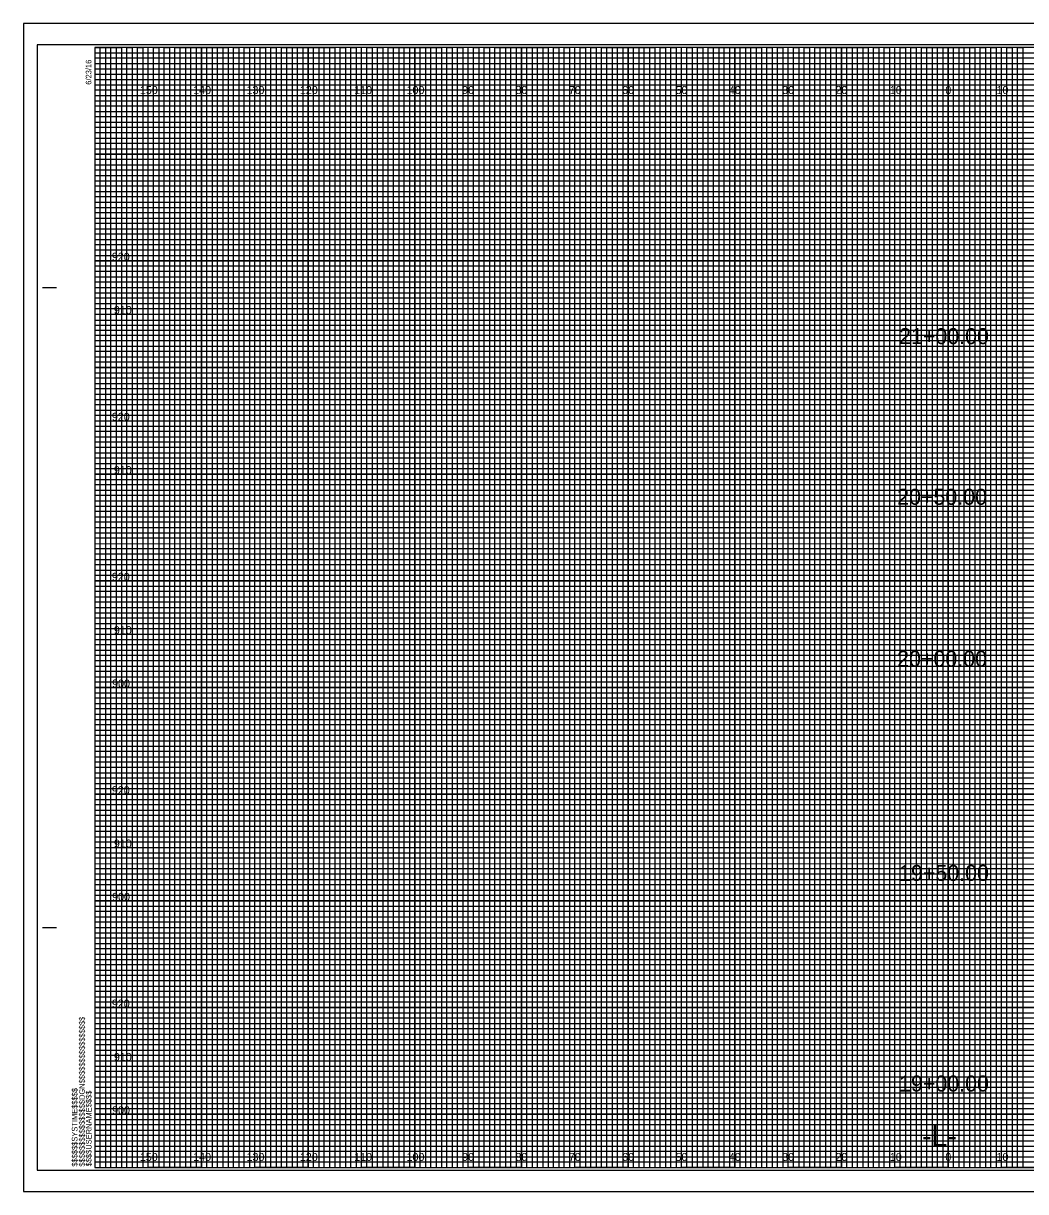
# Model space of a CAD drawing. Extents: x -13 to 364, y -4 to 214.
# Drawn here: x -13.4 to 174.5, y -4.5 to 214.5 of the extents above; entities that cross this region are included whole.
import ezdxf

# ---------------------------------------------------------------- set-up
doc = ezdxf.new("R2010")
doc.units = 0
for name, color, linetype in [('Prop SS Cut Line', 7, 'Continuous'), ('Prop SS Fill Line', 7, 'Continuous'), ('Prop XS Alignment Label', 7, 'Continuous'), ('Prop XS Elevation Labels', 7, 'Continuous'), ('Prop XS Label Text', 7, 'Continuous'), ('Prop XS Shear Point Label', 7, 'Continuous'), ('Prop XS Station Labels', 7, 'Continuous'), ('Scratch_Level_3', 7, 'Continuous'), ('Sheet Cross Section Grid Minor 2 CELL', 7, 'Continuous'), ('Sheet Cutting Line CELL', 7, 'Continuous'), ('Sheet DOT Grid CELL', 7, 'Continuous'), ('Sheet Plot Border Inside CELL', 7, 'Continuous'), ('Sheet Plot Border Outside CELL', 7, 'Continuous')]:
    doc.layers.add(name, color=color, linetype=linetype)

msp = doc.modelspace()

# ---------------------------------------------------------------- linework, layer by layer
at = {"layer": 'Prop SS Cut Line'}
for p, q in [((10, 210), (0, 210)), ((10, 0), (10, 210)), ((30, 210), (20, 210)), ((20, 210), (20, 0)), ((30, 0), (30, 210)), ((50, 210), (40, 210)), ((40, 210), (40, 0)), ((50, 0), (50, 210)), ((70, 210), (60, 210)), ((60, 210), (60, 0)), ((70, 0), (70, 210)), ((90, 210), (80, 210)), ((80, 210), (80, 0)), ((90, 0), (90, 210)), ((110, 210), (100, 210)), ((100, 210), (100, 0)), ((110, 0), (110, 210)), ((130, 210), (120, 210)), ((120, 210), (120, 0)), ((130, 0), (130, 210)), ((150, 210), (140, 210)), ((140, 210), (140, 0)), ((150, 0), (150, 210)), ((170, 210), (160, 210)), ((160, 210), (160, 0)), ((170, 0), (170, 210)), ((20, 0), (10, 0)), ((40, 0), (30, 0)), ((60, 0), (50, 0)), ((80, 0), (70, 0)), ((100, 0), (90, 0)), ((120, 0), (110, 0)), ((140, 0), (130, 0)), ((160, 0), (150, 0)), ((180, 0), (170, 0))]:
    msp.add_line(p, q, dxfattribs=at)
for points in [[(0, 200), (320, 200), (320, 190), (0, 190)], [(0, 180), (320, 180), (320, 170), (0, 170)], [(0, 160), (320, 160), (320, 150), (0, 150)], [(0, 140), (320, 140), (320, 130), (0, 130)], [(0, 120), (320, 120), (320, 110), (0, 110)], [(0, 100), (320, 100), (320, 90), (0, 90)], [(0, 80), (320, 80), (320, 70), (0, 70)], [(0, 60), (320, 60), (320, 50), (0, 50)], [(0, 40), (320, 40), (320, 30), (0, 30)], [(0, 20), (320, 20), (320, 10), (0, 10)]]:
    msp.add_lwpolyline(points, dxfattribs=at)
at = {"layer": 'Prop XS Label Text'}
for p, q in [((0, 209), (260, 209)), ((260, 207.98), (0, 207.98)), ((0, 207.98), (0, 207)), ((0, 207), (260, 207)), ((260, 205.89), (0, 205.89)), ((0, 205.89), (0, 204)), ((0, 204), (320, 204))]:
    msp.add_line(p, q, dxfattribs=at)
for points in [[(0, 203), (270, 203), (320, 203), (320, 202), (0, 202)], [(0, 201), (320, 201), (320, 199), (0, 199)], [(0, 198), (320, 198), (320, 197), (0, 196.98)], [(0, 196), (320, 196), (320, 194), (0, 194)], [(0, 193), (320, 193), (320, 192), (0, 192)], [(0, 191), (320, 191), (320, 189), (0, 189)], [(0, 188), (320, 188), (320, 187), (0, 187)], [(0, 186), (320, 186), (320, 184), (0, 184)], [(0, 183), (320, 183), (320, 182), (0, 182)], [(0, 181), (320, 181), (320, 179), (0, 179)], [(0, 178), (320, 178), (320, 177), (0, 177)], [(0, 176), (320, 176), (320, 173.95), (320, 173), (320, 172), (0, 172)], [(0, 174), (320, 174), (320, 173), (0, 173)], [(0, 171), (320, 171), (320, 169), (0, 169.03)], [(0, 169.03), (320, 169), (320, 168), (0, 168)], [(0, 167), (320, 167), (320, 166), (0, 166)], [(0, 164), (320, 164), (320, 163), (0, 163)], [(0, 162), (320, 162), (320, 161), (0, 161)], [(-0.07, 158.89), (320, 158.89), (320, 157.88), (-0.07, 157.88)], [(0, 157), (320, 157), (320, 156), (0, 156)], [(0, 154), (320, 154), (320, 153), (0, 153)], [(0, 152), (320, 152), (320, 151), (0, 151)], [(0, 149), (320, 149), (320, 148), (0, 148)], [(0, 147), (320, 147), (320, 146), (0, 146)], [(0, 144), (320, 144), (320, 143), (0, 143)], [(0, 142), (320, 142), (320, 141), (0, 141)], [(0, 139), (320, 139), (319.99, 137.98), (0, 138)], [(0, 137), (320, 137), (320, 136), (0, 136)], [(0, 134), (320, 134), (320, 133), (0, 133)], [(0, 132), (320, 132), (320, 131), (0, 131)], [(0, 129), (320, 129), (320, 128), (0, 128)], [(0, 127), (320, 127), (320, 126), (0, 126)], [(0, 124), (320, 124), (320, 123), (0, 123)], [(0, 122), (320, 122), (320, 121), (0, 121)], [(0, 119), (320, 119), (320, 118), (0, 118)], [(0, 116.99), (320.07, 116.91), (320, 116), (0, 116)], [(0, 114), (320, 114), (320, 113), (0, 113)], [(0, 112), (320, 112), (320, 111), (0, 111)], [(0, 109), (320, 109), (320, 108), (0, 108)], [(0, 107), (320, 107), (320, 106), (0, 106)], [(0, 104), (320, 104), (320, 103), (0, 103)], [(0, 102), (320, 102), (320, 101), (0, 101)], [(0, 99), (320, 99), (320, 98), (0, 98)], [(0, 97), (320, 97), (320, 96), (0, 96)], [(0, 94), (320, 94), (320, 93), (0, 93)], [(0, 92), (320, 92), (320, 91), (0, 91)], [(0, 89), (320, 89), (320, 88), (0, 88)], [(0, 87), (320, 87), (320, 86), (0, 86)], [(0, 84), (320, 84), (320, 83), (0, 83)], [(0, 82), (320, 82), (320, 81), (0, 81)], [(0, 79), (320, 79), (319.99, 77.98), (0, 78)], [(0, 77), (320, 77), (320, 76), (0, 76)], [(0, 74), (320, 74), (320, 73), (0, 73)], [(0, 72), (320, 72), (320, 71), (0, 71)], [(0, 69), (320, 69), (320, 68), (0, 68)], [(0, 67), (320, 67), (320, 66), (0, 66)], [(0, 64), (320, 64), (320, 63), (0, 63)], [(0, 62), (320, 62), (320, 61), (0, 61)], [(0, 59), (320, 59), (320, 58), (0, 58)], [(0, 56.99), (320.07, 56.91), (320, 56), (0, 56)], [(0, 54), (320, 54), (320, 53), (0, 53)], [(0, 52), (320, 52), (320, 51), (0, 51)], [(0, 49), (320, 49), (320, 48), (0, 48)], [(0, 47), (320, 47), (320, 46), (0, 46)], [(0, 44), (320, 44), (320, 43), (0, 43)], [(0, 42), (320, 42), (320, 41), (0, 41)], [(0, 39), (320, 39), (320, 38), (0, 38)], [(0, 37), (320, 37), (320, 36), (0, 36)], [(0, 34), (320, 34), (320, 33), (0, 33)], [(0, 32), (320, 32), (320, 31), (0, 31)], [(0, 29), (320, 29), (320, 28), (0, 28)], [(0, 27), (320, 27), (320, 26), (0, 26)], [(0, 24), (320, 24), (320, 23), (0, 23)], [(0, 22), (320, 22), (320, 21), (0, 21)], [(0, 19), (320, 19), (320, 18), (0, 18)], [(0, 17), (320, 17), (320, 16), (0, 16)], [(0, 14), (320, 14), (320, 13), (0, 13)], [(0, 12), (320, 12), (320, 11), (0, 11)], [(0, 9), (320, 9), (320, 8), (0, 8)], [(0, 7), (320, 7), (320, 6), (0, 6)], [(0, 4), (320, 4), (320, 3), (0, 3)], [(0, 2), (320, 2), (320, 1), (0, 1)]]:
    msp.add_lwpolyline(points, dxfattribs=at)
at = {"layer": 'Prop XS Shear Point Label'}
for points in [[(0, 210), (5, 210), (5, 0), (15, 0), (15, 210), (25, 210), (25, 0), (35, 0), (35, 210), (45, 210), (45, 0), (55, 0), (55, 210), (65, 210), (65, 0), (75, 0), (75, 210), (85, 210), (85, 0), (95, 0), (95, 210), (105, 210), (105, 0), (115, 0), (115, 210), (125, 210), (125, 0), (135, 0), (135, 210), (145, 210), (145, 0), (155, 0), (155, 210), (165, 210), (165, 0), (175, 0)], [(0, 205), (275, 205)], [(0, 185), (320, 185), (320, 195), (0, 195)], [(0, 165), (320, 165), (320, 175), (0, 175)], [(0, 145), (320, 145), (320, 155), (0, 155)], [(0, 125), (320, 125), (320, 135), (0, 135)], [(0, 105), (320, 105), (320, 115), (0, 115)], [(0, 85), (320, 85), (320, 95), (0, 95)], [(0, 65), (320, 65), (320, 75), (0, 75)], [(0, 45), (320, 45), (320, 55), (0, 55)], [(0, 25), (320, 25), (320, 35), (0, 35)], [(0, 5), (320, 5), (320, 15), (0, 15)]]:
    msp.add_lwpolyline(points, dxfattribs=at)
at = {"layer": 'Scratch_Level_3'}
for p, q in [((-9.8, 165), (-7.3, 165)), ((-9.7, 165), (-7.2, 165)), ((-9.8, 45), (-7.3, 45)), ((-9.7, 45), (-7.2, 45)), ((0, 0), (0, 0)), ((0, 0), (0, 0)), ((0, 0), (0, 0)), ((0, 0), (0, 0)), ((0, 0), (0, 0)), ((0, 0), (0, 0)), ((0, 0), (0, 0))]:
    msp.add_line(p, q, dxfattribs=at)
msp.add_lwpolyline([(320, 210), (0, 210), (0, 0), (320, 0)], close=True, dxfattribs=at)
at = {"layer": 'Sheet Cross Section Grid Minor 2 CELL'}
for points in [[(0, 0), (1, 0), (1, 210), (2, 210), (2, 0)], [(2, 0), (3, 0), (3, 210), (4, 210), (4, 0)], [(5, 0), (6, 0), (6, 210), (7, 210), (7, 0)], [(7, 0), (8, 0), (8, 210), (9, 210), (9, 0)], [(10, 0), (11, 0), (11, 210), (12, 210), (12, 0)], [(12, 0), (13, 0), (13, 210), (14, 210), (14, 0)], [(15, 0), (16, 0), (16, 210), (17, 210), (17, 0)], [(17, 0), (18, 0), (18, 210), (19, 210), (19, 0)], [(20, 0), (21, 0), (21, 210), (22, 210), (22, 0)], [(22, 0), (23, 0), (23, 210), (24, 210), (24, 0)], [(25, 0), (26, 0), (26, 210), (27, 210), (27, 0)], [(27, 0), (28, 0), (28, 210), (29, 210), (29, 0)], [(30, 0), (31, 0), (31, 210), (32, 210), (32, 0)], [(32, 0), (33, 0), (33, 210), (34, 210), (34, 0)], [(35, 0), (36, 0), (36, 210), (37, 210), (37, 0)], [(37, 0), (38, 0), (38, 210), (39, 210), (39, 0)], [(40, 0), (41, 0), (41, 210), (42, 210), (42, 0)], [(42, 0), (43, 0), (43, 210), (44, 210), (44, 0)], [(45, 0), (46, 0), (46, 210), (47, 210), (47, 0)], [(47, 0), (48, 0), (48, 210), (49, 210), (49, 0)], [(50, 0), (51, 0), (51, 210), (52, 210), (52, 0)], [(52, 0), (53, 0), (53, 210), (54, 210), (54, 0)], [(55, 0), (56, 0), (56, 210), (57, 210), (57, 0)], [(57, 0), (58, 0), (58, 210), (59, 210), (59, 0)], [(60, 0), (61, 0), (61, 210), (62, 210), (62, 0)], [(62, 0), (63, 0), (63, 210), (64, 210), (64, 0)], [(65, 0), (66, 0), (66, 210), (67, 210), (67, 0)], [(67, 0), (68, 0), (68, 210), (69, 210), (69, 0)], [(70, 0), (71, 0), (71, 210), (72, 210), (72, 0)], [(72, 0), (73, 0), (73, 210), (74, 210), (74, 0)], [(75, 0), (76, 0), (76, 210), (77, 210), (77, 0)], [(77, 0), (78, 0), (78, 210), (79, 210), (79, 0)], [(80, 0), (81, 0), (81, 210), (82, 210), (82, 0)], [(82, 0), (83, 0), (83, 210), (84, 210), (84, 0)], [(85, 0), (86, 0), (86, 210), (87, 210), (87, 0)], [(87, 0), (88, 0), (88, 210), (89, 210), (89, 0)], [(90, 0), (91, 0), (91, 210), (92, 210), (92, 0)], [(92, 0), (93, 0), (93, 210), (94, 210), (94, 0)], [(95, 0), (96, 0), (96, 210), (97, 210), (97, 0)], [(97, 0), (98, 0), (98, 210), (99, 210), (99, 0)], [(100, 0), (101, 0), (101, 210), (102, 210), (102, 0)], [(102, 0), (103, 0), (103, 210), (104, 210), (104, 0)], [(105, 0), (106, 0), (106, 210), (107, 210), (107, 0)], [(107, 0), (108, 0), (108, 210), (109, 210), (109, 0)], [(110, 0), (111, 0), (111, 210), (112, 210), (112, 0)], [(112, 0), (113, 0), (113, 210), (114, 210), (114, 0)], [(115, 0), (116, 0), (116, 210), (117, 210), (117, 0)], [(117, 0), (118, 0), (118, 210), (119, 210), (119, 0)], [(120, 0), (121, 0), (121, 210), (122, 210), (122, 0)], [(122, 0), (123, 0), (123, 210), (124, 210), (124, 0)], [(125, 0), (126, 0), (126, 210), (127, 210), (127, 0)], [(127, 0), (128, 0), (128, 210), (129, 210), (129, 0)], [(130, 0), (131, 0), (131, 210), (132, 210), (132, 0)], [(132, 0), (133, 0), (133, 210), (134, 210), (134, 0)], [(135, 0), (136, 0), (136, 210), (137, 210), (137, 0)], [(137, 0), (138, 0), (138, 210), (139, 210), (139, 0)], [(140, 0), (141, 0), (141, 210), (142, 210), (142, 0)], [(142, 0), (143, 0), (143, 210), (144, 210), (144, 0)], [(145, 0), (146, 0), (146, 210), (147, 210), (147, 0)], [(147, 0), (148, 0), (148, 210), (149, 210), (149, 0)], [(150, 0), (151, 0), (151, 210), (152, 210), (152, 0)], [(152, 0), (153, 0), (153, 210), (154, 210), (154, 0)], [(155, 0), (156, 0), (156, 210), (157, 210), (157, 0)], [(157, 0), (158, 0), (158, 210), (159, 210), (159, 0)], [(160, 0), (161, 0), (161, 210), (162, 210), (162, 0)], [(162, 0), (163, 0), (163, 210), (164, 210), (164, 0)], [(165, 0), (166, 0), (166, 210), (167, 210), (167, 0)], [(167, 0), (168, 0), (168, 210), (169, 210), (169, 0)], [(170, 0), (171, 0), (171, 210), (172, 210), (172, 0)], [(172, 0), (173, 0), (173, 210), (174, 210), (174, 0)]]:
    msp.add_lwpolyline(points, dxfattribs=at)
at = {"layer": 'Sheet Cutting Line CELL'}
for p, q in [((323.3, 214.5), (-13.4, 214.5)), ((-13.4, 214.5), (-13.4, -4.5)), ((-13.4, -4.5), (323.3, -4.5))]:
    msp.add_line(p, q, dxfattribs=at)
at = {"layer": 'Sheet DOT Grid CELL'}
for p, q in [((10, 0), (10, 210)), ((20, 0), (20, 210)), ((30, 0), (30, 210)), ((40, 0), (40, 210)), ((50, 0), (50, 210)), ((60, 0), (60, 210)), ((70, 0), (70, 210)), ((80, 0), (80, 210)), ((90, 0), (90, 210)), ((100, 0), (100, 210)), ((110, 0), (110, 210)), ((120, 0), (120, 210)), ((130, 0), (130, 210)), ((140, 0), (140, 210)), ((150, 0), (150, 210)), ((160, 0), (160, 210)), ((170, 0), (170, 210)), ((0, 200), (320, 200)), ((0, 190), (320, 190)), ((0, 180), (320, 180)), ((0, 170), (320, 170)), ((0, 160), (320, 160)), ((0, 150), (320, 150)), ((0, 140), (320, 140)), ((0, 130), (320, 130)), ((0, 120), (320, 120)), ((0, 110), (320, 110)), ((0, 100), (320, 100)), ((0, 90), (320, 90)), ((0, 80), (320, 80)), ((0, 70), (320, 70)), ((0, 60), (320, 60)), ((0, 50), (320, 50)), ((0, 40), (320, 40)), ((0, 30), (320, 30)), ((0, 20), (320, 20)), ((0, 10), (320, 10))]:
    msp.add_line(p, q, dxfattribs=at)
at = {"layer": 'Sheet Plot Border Inside CELL'}
msp.add_lwpolyline([(-10.8, -0.5), (322.4, -0.5), (322.4, 210.5), (-10.8, 210.5)], close=True, dxfattribs=at)
at = {"layer": 'Sheet Plot Border Outside CELL'}
msp.add_lwpolyline([(-13.4, -4.5), (323.3, -4.5), (323.3, 214.5), (-13.4, 214.5)], close=True, dxfattribs=at)

# ---------------------------------------------------------------- texts
at = {"layer": 'Prop SS Fill Line'}
for s, p in [('150', (8.44, 201.25)), ('140', (18.44, 201.25)), ('130', (28.44, 201.25)), ('120', (38.44, 201.25)), ('110', (48.62, 201.25)), ('100', (58.44, 201.25)), ('90', (68.86, 201.25)), ('80', (78.86, 201.25)), ('70', (88.86, 201.25)), ('60', (98.86, 201.25)), ('50', (108.86, 201.25)), ('40', (118.86, 201.25)), ('30', (128.86, 201.25)), ('20', (138.86, 201.25)), ('10', (149.04, 201.25)), ('0', (159.45, 201.25)), ('0', (159.45, 201.25)), ('10', (169.04, 201.25)), ('150', (8.44, 1.25)), ('140', (18.44, 1.25)), ('130', (28.44, 1.25)), ('120', (38.44, 1.25)), ('110', (48.62, 1.25)), ('100', (58.44, 1.25)), ('90', (68.86, 1.25)), ('80', (78.86, 1.25)), ('70', (88.86, 1.25)), ('60', (98.86, 1.25)), ('50', (108.86, 1.25)), ('40', (118.86, 1.25)), ('30', (128.86, 1.25)), ('20', (138.86, 1.25)), ('10', (149.04, 1.25)), ('0', (159.45, 1.25)), ('0', (159.45, 1.25)), ('10', (169.04, 1.25))]:
    msp.add_text(s, height=1.5, dxfattribs=at).set_placement(p)
at = {"layer": 'Prop XS Alignment Label'}
msp.add_text('-L-', height=4, dxfattribs=at).set_placement((155.06, 4))
at = {"layer": 'Prop XS Elevation Labels'}
for s, p in [('920', (3.19, 170)), ('910', (3.57, 160)), ('920', (3.19, 140)), ('910', (3.57, 130)), ('920', (3.19, 110)), ('910', (3.57, 100)), ('900', (3.24, 90)), ('920', (3.19, 70)), ('910', (3.57, 60)), ('900', (3.24, 50)), ('920', (3.19, 30)), ('910', (3.57, 20)), ('900', (3.24, 10))]:
    msp.add_text(s, height=1.5, dxfattribs=at).set_placement(p)
at = {"layer": 'Prop XS Station Labels'}
for s, p in [('21+00.00', (150.77, 154.37)), ('20+50.00', (150.41, 124.26)), ('20+00.00', (150.41, 93.9)), ('19+50.00', (150.77, 53.74)), ('19+00.00', (150.77, 14.27))]:
    msp.add_text(s, height=3, dxfattribs=at).set_placement(p)
at = {"layer": 'Scratch_Level_3'}
for s, p in [('6/23/16', (-0.65, 203)), ('$$$$$$$$$$$$$$$$DGN$$$$$$$$$$$$$$$$', (-1.88, 0.18)), ('$$$$$$SYSTIME$$$$$', (-3.26, 0.18)), ('$$$$USERNAME$$$$', (-0.62, 0.23))]:
    msp.add_text(s, height=1.05, rotation=90, dxfattribs=at).set_placement(p)

doc.saveas('drawing.dxf')
